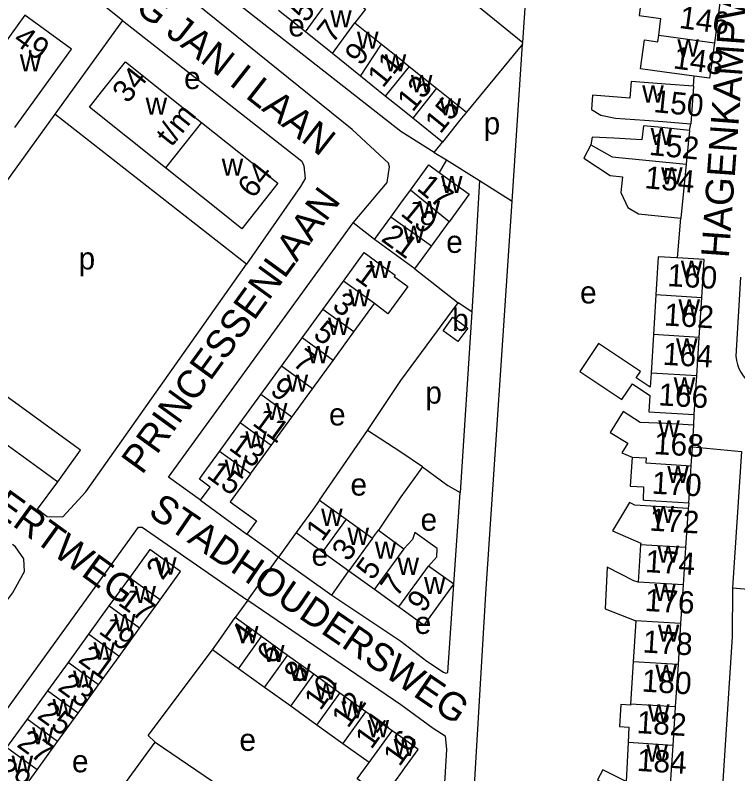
# Model space of a CAD drawing. Extents: x 159700 to 161346, y 381730 to 382922.
# Drawn here: x 160430.8 to 160560.5, y 382445.9 to 382582.1 of the extents above; entities that cross this region are included whole.
import ezdxf

# ---------------------------------------------------------------- set-up
doc = ezdxf.new("R2010")
doc.units = 0
for name, color, linetype in [('BLT_Basislijn', 7, 'Continuous'), ('BLT_Bebouwing', 7, 'Continuous'), ('BLT_Centroide', 7, 'Continuous'), ('BLT_Huisnummer', 7, 'Continuous'), ('BLT_Huisnummer_ tussenligend', 7, 'Continuous'), ('BLT_Huisnummer_reeks', 7, 'Continuous'), ('BLT_Onderverdeling_panden', 7, 'Continuous'), ('BLT_Straatnaam', 7, 'Continuous'), ('BLT_Vlakafsluiter', 7, 'Continuous')]:
    doc.layers.add(name, color=color, linetype=linetype)

msp = doc.modelspace()

# ---------------------------------------------------------------- linework, layer by layer
at = {"layer": 'BLT_Basislijn'}
for p, q in [((160521.9, 382577.2), (160522.55, 382587.01)), ((160450.08, 382581.13), (160437.89, 382564.3)), ((160521.88, 382576.89), (160511.79, 382564.68)), ((160521.88, 382576.89), (160521.9, 382577.2)), ((160552.56, 382569.33), (160552.67, 382571.16)), ((160472.29, 382537.4), (160437.89, 382564.3)), ((160551.83, 382561.41), (160552.04, 382562.6)), ((160506.02, 382557.47), (160507.48, 382559.32)), ((160506.02, 382557.47), (160508.2, 382556.11)), ((160508.2, 382556.11), (160506.92, 382553.88)), ((160508.2, 382556.11), (160514.16, 382552.39)), ((160514.16, 382552.39), (160519.99, 382548.74)), ((160495.27, 382541.84), (160491.46, 382544.8)), ((160549.67, 382538.56), (160550.27, 382545.68)), ((160502.54, 382536.57), (160510.32, 382530.44)), ((160560.96, 382535.06), (160560.13, 382520.87)), ((160512.73, 382528.86), (160510.32, 382530.44)), ((160512.73, 382528.86), (160510.64, 382496.44)), ((160552.6, 382508.49), (160552.67, 382510.41)), ((160485.43, 382495.06), (160494.02, 382507.56)), ((160552.35, 382504.63), (160561.18, 382503.79)), ((160561.18, 382503.79), (160559.55, 382479.31)), ((160464.08, 382495.04), (160458.31, 382499.17)), ((160434.82, 382493.43), (160438.44, 382498.36)), ((160509.52, 382479.96), (160510.64, 382496.44)), ((160551.7, 382494.52), (160551.58, 382493.56)), ((160477.01, 382485.58), (160472.36, 382488.95)), ((160481.23, 382489.22), (160478.07, 382484.82)), ((160477.01, 382485.58), (160478.07, 382484.82)), ((160478.07, 382484.82), (160487.6, 382477.99)), ((160487.6, 382477.99), (160490.7, 382482.38)), ((160559.55, 382479.31), (160564.17, 382478.9)), ((160472.54, 382477.1), (160470.28, 382473.97)), ((160455.93, 382451.62), (160486.17, 382431.07))]:
    msp.add_line(p, q, dxfattribs=at)
for points in [[(160482.89, 382608.65), (160500, 382594.99), (160521.9, 382577.2)], [(160491.46, 382544.8), (160497.56, 382552.05), (160497.99, 382554.89), (160497.77, 382555.53), (160491.25, 382561.57), (160440.32, 382602.72)], [(160450.08, 382581.13), (160435.03, 382593.18), (160433.21, 382592.93), (160424.89, 382581.85), (160387.63, 382530.18), (160388, 382528.33), (160391.85, 382526)], [(160506.02, 382557.47), (160500, 382561.24), (160466, 382587.92)], [(160450.08, 382581.13), (160482.23, 382555.86), (160482.6, 382555.07), (160482.81, 382552.8), (160482.02, 382551.33), (160472.29, 382537.4)], [(160519.99, 382548.74), (160521.88, 382576.89)], [(160437.89, 382564.3), (160411.53, 382527.84), (160403.97, 382516.97)], [(160514.16, 382552.39), (160512.98, 382532.81), (160512.73, 382528.86)], [(160512.9, 382437.77), (160515.27, 382478.21), (160519.99, 382548.74)], [(160458.31, 382499.17), (160491.46, 382544.8)], [(160434.82, 382493.43), (160436.55, 382492.11), (160439.35, 382492.08), (160443.49, 382496.52), (160472.29, 382537.4)], [(160494.02, 382507.56), (160500, 382516.52), (160510.32, 382530.44)], [(160560.13, 382520.87), (160560.24, 382520.12), (160560.44, 382519.39), (160560.71, 382518.68), (160561.05, 382518.01), (160561.46, 382517.37), (160561.94, 382516.78), (160562.47, 382516.25), (160563.06, 382515.77), (160563.7, 382515.36), (160564.38, 382515.02), (160565.08, 382514.76), (160565.82, 382514.56), (160566.57, 382514.45), (160567.08, 382514.42)], [(160503.93, 382501.04), (160500, 382503.69), (160494.02, 382507.56)], [(160503.93, 382501.04), (160500, 382495.65), (160495.98, 382489.64)], [(160503.93, 382501.04), (160508.47, 382497.7), (160510.64, 382496.44)], [(160430.4, 382416.72), (160418.93, 382425.29), (160413.76, 382429.1), (160410.56, 382431.49), (160411.73, 382433.33), (160452.93, 382490.2), (160453.57, 382490.2), (160472.31, 382477.25), (160472.54, 382477.1)], [(160423.27, 382469.03), (160430.29, 382478.37), (160432.44, 382482.25), (160432.32, 382484.51), (160430.82, 382486.67), (160430.3, 382487.08)], [(160487.6, 382477.99), (160500, 382469.72), (160504.66, 382466.15), (160507.69, 382464.21), (160508.1, 382464.02), (160508.46, 382464.1), (160509.52, 382479.96)], [(160559.55, 382479.31), (160559.48, 382470.53), (160555.29, 382405.8)], [(160472.54, 382477.1), (160500, 382458.38), (160505.82, 382454.14), (160507.95, 382452.76), (160508.2, 382450.32), (160507.17, 382433.33), (160506.17, 382416.78)], [(160455.93, 382451.62), (160454.67, 382452.8), (160466.18, 382468.17)], [(160432.72, 382419.8), (160442.6, 382433.33), (160455.93, 382451.62)]]:
    msp.add_lwpolyline(points, dxfattribs=at)
at = {"layer": 'BLT_Bebouwing'}
for p, q in [((160482.88, 382579.09), (160478.08, 382582.95)), ((160546.3, 382578.52), (160546.71, 382581.52)), ((160491.77, 382580.72), (160496.56, 382576.87)), ((160487.72, 382575.2), (160482.88, 382579.09)), ((160492.75, 382571.16), (160487.72, 382575.2)), ((160501.51, 382572.9), (160506.42, 382568.97)), ((160497.2, 382567.58), (160492.75, 382571.16)), ((160552.56, 382569.33), (160552.04, 382562.6)), ((160506.42, 382568.97), (160511.79, 382564.68)), ((160507.48, 382559.32), (160502.15, 382563.6)), ((160551.83, 382561.41), (160551.23, 382555.34)), ((160505.5, 382540.63), (160508.71, 382545.03)), ((160502.54, 382536.57), (160505.5, 382540.63)), ((160486.01, 382529.28), (160489.72, 382534.37)), ((160545.79, 382531.88), (160545.36, 382524.76)), ((160553.57, 382524.26), (160554.03, 382531.39)), ((160491.57, 382525.23), (160495.27, 382530.32)), ((160482.3, 382524.18), (160486.01, 382529.28)), ((160487.86, 382520.14), (160491.57, 382525.23)), ((160545.36, 382524.76), (160544.94, 382517.83)), ((160478.59, 382519.09), (160482.3, 382524.18)), ((160553.12, 382517.34), (160553.57, 382524.26)), ((160474.88, 382513.99), (160478.59, 382519.09)), ((160484.15, 382515.04), (160487.86, 382520.14)), ((160413.84, 382516.2), (160436.18, 382500)), ((160552.67, 382510.41), (160553.12, 382517.34)), ((160480.44, 382509.95), (160484.15, 382515.04)), ((160471.17, 382508.9), (160474.88, 382513.99)), ((160476.73, 382504.85), (160480.44, 382509.95)), ((160467.46, 382503.8), (160471.17, 382508.9)), ((160552.35, 382504.63), (160552.6, 382508.49)), ((160473.2, 382500), (160476.73, 382504.85)), ((160552.13, 382501.24), (160552.35, 382504.63)), ((160464.69, 382500), (160467.46, 382503.8)), ((160541.51, 382502.75), (160541.19, 382497.58)), ((160551.7, 382494.52), (160552.13, 382501.24)), ((160436.18, 382500), (160438.44, 382498.36)), ((160438.44, 382498.36), (160439.64, 382500)), ((160473.02, 382499.76), (160473.2, 382500)), ((160464.08, 382495.04), (160472.36, 382488.95)), ((160485.43, 382495.06), (160490.17, 382491.65)), ((160543.79, 382495.01), (160543.54, 382495.03)), ((160551.7, 382494.52), (160543.79, 382495.01)), ((160551.58, 382493.56), (160551.13, 382486.56)), ((160490.17, 382491.65), (160494.92, 382488.24)), ((160481.23, 382489.22), (160485.96, 382485.8)), ((160494.92, 382488.24), (160495.98, 382489.64)), ((160495.98, 382489.64), (160500.57, 382486.34)), ((160543.05, 382487.06), (160542.62, 382480.36)), ((160551.13, 382486.56), (160550.69, 382479.85)), ((160485.96, 382485.8), (160490.7, 382482.38)), ((160490.7, 382482.38), (160495.29, 382479.06)), ((160509.52, 382479.96), (160504.96, 382483.19)), ((160451.3, 382481.14), (160447.62, 382476.06)), ((160550.69, 382479.85), (160550.24, 382472.9)), ((160495.29, 382479.06), (160499.67, 382475.9)), ((160453.12, 382472.08), (160456.8, 382477.16)), ((160447.62, 382476.06), (160443.94, 382470.98)), ((160475.01, 382470.56), (160470.28, 382473.97)), ((160542.18, 382473.4), (160541.73, 382466.05)), ((160550.24, 382472.9), (160549.77, 382465.55)), ((160449.44, 382467), (160453.12, 382472.08)), ((160443.94, 382470.98), (160440.27, 382465.9)), ((160479.69, 382467.18), (160475.01, 382470.56)), ((160470.87, 382464.8), (160466.18, 382468.17)), ((160484.38, 382463.81), (160479.69, 382467.18)), ((160440.27, 382465.9), (160436.59, 382460.82)), ((160445.76, 382461.92), (160449.44, 382467)), ((160541.73, 382466.05), (160541.25, 382458.45)), ((160475.56, 382461.43), (160470.87, 382464.8)), ((160549.77, 382465.55), (160549.27, 382457.95)), ((160489.06, 382460.43), (160484.38, 382463.81)), ((160442.09, 382456.84), (160445.76, 382461.92)), ((160436.59, 382460.82), (160432.91, 382455.74)), ((160480.24, 382458.06), (160475.56, 382461.43)), ((160493.75, 382457.06), (160489.06, 382460.43)), ((160484.93, 382454.69), (160480.24, 382458.06)), ((160549.27, 382457.95), (160548.83, 382451.03)), ((160438.41, 382451.76), (160442.09, 382456.84)), ((160498.44, 382453.68), (160493.75, 382457.06)), ((160432.91, 382455.74), (160429.23, 382450.66)), ((160489.62, 382451.32), (160484.93, 382454.69)), ((160434.73, 382446.68), (160438.41, 382451.76)), ((160494.32, 382447.95), (160489.62, 382451.32)), ((160540.79, 382451.53), (160540.45, 382444.54)), ((160548.83, 382451.03), (160548.37, 382444.04)), ((160431.05, 382441.6), (160434.73, 382446.68))]:
    msp.add_line(p, q, dxfattribs=at)
for points in [[(160544.03, 382592.06), (160542.8, 382582.06), (160546.71, 382581.52)], [(160486.92, 382584.62), (160488.8, 382586.98), (160493.69, 382583.14), (160491.77, 382580.72)], [(160553.63, 382585.21), (160557.34, 382584.7), (160556.29, 382577.15)], [(160430.72, 382561.95), (160440.9, 382575.98), (160432.49, 382582.07), (160422.32, 382568.04)], [(160552.67, 382571.16), (160550.46, 382571.46), (160547.36, 382571.89), (160543.06, 382572.48), (160543.77, 382577.65)], [(160543.77, 382577.65), (160546.14, 382577.33), (160546.3, 382578.52)], [(160496.56, 382576.87), (160500, 382574.11), (160501.51, 382572.9)], [(160556.29, 382577.15), (160555.42, 382570.78), (160552.67, 382571.16)], [(160457.78, 382554.69), (160444.11, 382565.6), (160446.3, 382568.35), (160450.61, 382573.72), (160464.26, 382562.82)], [(160552.56, 382569.33), (160547.58, 382569.72), (160541.33, 382570.21), (160541.09, 382567.2)], [(160502.15, 382563.6), (160500, 382565.33), (160497.2, 382567.58)], [(160541.09, 382567.2), (160534.42, 382567.72), (160534.23, 382565.18), (160535.94, 382564.17), (160538.54, 382563.61), (160543.73, 382563.25), (160547.06, 382562.99), (160552.04, 382562.6)], [(160511.79, 382564.68), (160510.61, 382563.22), (160507.48, 382559.32)], [(160464.26, 382562.82), (160477.92, 382551.92), (160471.46, 382543.77), (160467.46, 382546.96), (160457.78, 382554.69)], [(160551.83, 382561.41), (160546.85, 382561.91), (160543.55, 382562.23), (160543.3, 382559.73), (160538.26, 382560), (160534.37, 382560.2), (160534.13, 382558.83)], [(160534.13, 382558.83), (160532.86, 382556.42), (160537.6, 382553.3), (160539.81, 382553.09), (160539.53, 382550.28), (160540.74, 382547.57), (160542.7, 382546.42), (160550.27, 382545.68)], [(160501.72, 382550.71), (160505.04, 382555.26), (160506.92, 382553.88)], [(160551.23, 382555.34), (160550.27, 382545.68)], [(160506.92, 382553.88), (160509.07, 382552.31), (160512.29, 382549.95), (160508.71, 382545.03)], [(160498.19, 382545.85), (160500, 382548.34), (160501.72, 382550.71)], [(160495.27, 382541.84), (160498.19, 382545.85)], [(160502.54, 382536.57), (160495.27, 382541.84)], [(160489.72, 382534.37), (160493.46, 382539.51), (160497.47, 382536.53), (160498.98, 382535.41), (160498.8, 382535.17), (160501.25, 382533.39), (160497.7, 382528.51), (160495.27, 382530.32)], [(160549.67, 382538.56), (160549.57, 382538.56), (160546.2, 382538.72), (160545.79, 382531.88)], [(160554.03, 382531.39), (160554.48, 382538.27), (160549.67, 382538.56)], [(160544.94, 382517.83), (160544.79, 382515.31), (160542.28, 382516.98), (160543.06, 382518.15), (160535.49, 382523.19), (160532.14, 382518.15), (160539.71, 382513.12), (160541.57, 382515.9), (160544.7, 382513.82), (160544.52, 382510.9), (160552.67, 382510.41)], [(160439.64, 382500), (160442.54, 382504), (160417.93, 382521.84), (160413.84, 382516.2)], [(160552.6, 382508.49), (160547.61, 382508.79), (160542.98, 382508.97), (160539.9, 382510.94), (160537.58, 382507.18), (160540.73, 382505.29), (160539.68, 382503.54), (160541.51, 382502.75)], [(160464.08, 382495.04), (160465.81, 382497.41), (160463.85, 382498.84), (160464.69, 382500)], [(160473.02, 382499.76), (160472.26, 382498.71), (160469.39, 382494.76), (160474.09, 382491.33), (160472.36, 382488.95)], [(160541.19, 382497.58), (160543.59, 382497.43), (160543.54, 382495.03)], [(160485.43, 382495.06), (160484.15, 382493.28), (160481.23, 382489.22)], [(160551.58, 382493.56), (160542.01, 382494.15), (160541.03, 382494.66), (160537.98, 382489.54), (160543.07, 382487.31), (160543.05, 382487.06)], [(160504.96, 382483.19), (160506.45, 382484.89), (160506.55, 382486.35), (160502.51, 382489.24), (160502.08, 382488.01), (160500.57, 382486.34)], [(160456.8, 382477.16), (160460.47, 382482.23), (160454.98, 382486.21), (160451.3, 382481.14)], [(160542.62, 382480.36), (160541.86, 382480.55), (160537.06, 382483.04), (160536.66, 382475.53), (160542.18, 382473.4)], [(160499.67, 382475.9), (160500, 382475.66), (160504.2, 382472.62), (160507.12, 382476.68), (160509.52, 382479.96)], [(160466.18, 382468.17), (160467.39, 382469.89), (160470.28, 382473.97)], [(160541.25, 382458.45), (160541.24, 382458.25), (160539.51, 382458.36), (160539.26, 382454.43), (160540.96, 382454.33), (160540.79, 382451.53)], [(160500.73, 382446.99), (160503.11, 382450.32), (160500, 382452.55), (160498.44, 382453.68)], [(160496.92, 382441.69), (160492.15, 382445.02), (160494.32, 382447.95)], [(160496.92, 382441.69), (160500, 382445.97), (160500.73, 382446.99)], [(160540.45, 382444.54), (160536.25, 382446.67), (160535.32, 382444.84), (160536.05, 382444.46), (160534.32, 382441.05), (160540.06, 382438.14), (160540.03, 382437.64), (160547.92, 382437.12)]]:
    msp.add_lwpolyline(points, dxfattribs=at)
msp.add_lwpolyline([(160507.59, 382525.44), (160509.34, 382527.87), (160512.02, 382525.94), (160510.27, 382523.51)], close=True, dxfattribs=at)
at = {"layer": 'BLT_Onderverdeling_panden'}
for p, q in [((160482.88, 382579.09), (160486.92, 382584.62)), ((160487.72, 382575.2), (160491.77, 382580.72)), ((160546.3, 382578.52), (160556.29, 382577.15)), ((160492.75, 382571.16), (160496.56, 382576.87)), ((160501.51, 382572.9), (160497.2, 382567.58)), ((160506.42, 382568.97), (160502.15, 382563.6)), ((160464.26, 382562.82), (160457.78, 382554.69)), ((160508.71, 382545.03), (160501.72, 382550.71)), ((160505.5, 382540.63), (160498.19, 382545.85)), ((160495.27, 382530.32), (160489.72, 382534.37)), ((160554.03, 382531.39), (160545.79, 382531.88)), ((160491.57, 382525.23), (160486.01, 382529.28)), ((160553.57, 382524.26), (160545.36, 382524.76)), ((160487.86, 382520.14), (160482.3, 382524.18)), ((160484.15, 382515.04), (160478.59, 382519.09)), ((160553.12, 382517.34), (160544.94, 382517.83)), ((160480.44, 382509.95), (160474.88, 382513.99)), ((160476.73, 382504.85), (160471.17, 382508.9)), ((160473.02, 382499.76), (160467.46, 382503.8)), ((160490.17, 382491.65), (160485.96, 382485.8)), ((160494.92, 382488.24), (160490.7, 382482.38)), ((160500.57, 382486.34), (160495.29, 382479.06)), ((160551.13, 382486.56), (160543.05, 382487.06)), ((160499.67, 382475.9), (160504.96, 382483.19)), ((160456.8, 382477.16), (160451.3, 382481.14)), ((160550.69, 382479.85), (160542.62, 382480.36)), ((160453.12, 382472.08), (160447.62, 382476.06)), ((160550.24, 382472.9), (160542.18, 382473.4)), ((160449.44, 382467), (160443.94, 382470.98)), ((160470.87, 382464.8), (160475.01, 382470.56)), ((160475.56, 382461.43), (160479.69, 382467.18)), ((160445.76, 382461.92), (160440.27, 382465.9)), ((160549.77, 382465.55), (160541.73, 382466.05)), ((160480.24, 382458.06), (160484.38, 382463.81)), ((160442.09, 382456.84), (160436.59, 382460.82)), ((160484.93, 382454.69), (160489.06, 382460.43)), ((160549.27, 382457.95), (160541.25, 382458.45)), ((160489.62, 382451.32), (160493.75, 382457.06)), ((160438.41, 382451.76), (160432.91, 382455.74)), ((160494.32, 382447.95), (160498.44, 382453.68)), ((160548.83, 382451.03), (160540.79, 382451.53)), ((160434.73, 382446.68), (160429.23, 382450.66))]:
    msp.add_line(p, q, dxfattribs=at)
for points in [[(160534.13, 382558.83), (160537.93, 382556.65), (160551.23, 382555.34)], [(160541.51, 382502.75), (160544.04, 382502.62), (160543.96, 382501.72), (160552.13, 382501.24)]]:
    msp.add_lwpolyline(points, dxfattribs=at)
at = {"layer": 'BLT_Vlakafsluiter'}
msp.add_line((160472.54, 382477.1), (160478.07, 382484.82), dxfattribs=at)

# ---------------------------------------------------------------- texts
at = {"layer": 'BLT_Centroide'}
for s, p in [('w', (160487.33, 382579.91)), ('e', (160479.81, 382578.28)), ('w', (160492.14, 382576.05)), ('w', (160549.66, 382574.66)), ('w', (160431.61, 382572)), ('w', (160497.12, 382572.02)), ('e', (160461.11, 382568.83)), ('w', (160501.81, 382568.27)), ('w', (160543.34, 382566.41)), ('w', (160454.2, 382564.22)), ('w', (160506.97, 382564.12)), ('p', (160514.88, 382560.7)), ('w', (160544.85, 382558.78)), ('w', (160467.86, 382553.28)), ('w', (160546.73, 382551.72)), ('w', (160507.22, 382550.16)), ('w', (160503.18, 382545.66)), ('w', (160500.41, 382541.22)), ('e', (160508.16, 382539.43)), ('p', (160442.17, 382536.45)), ('w', (160494.37, 382534.91)), ('w', (160550.27, 382534.97)), ('w', (160490.64, 382529.81)), ('e', (160532.18, 382530.35)), ('w', (160549.85, 382528)), ('b', (160509.23, 382525.42)), ('w', (160486.93, 382524.72)), ('w', (160549.42, 382521)), ('w', (160483.23, 382519.62)), ('w', (160479.52, 382514.53)), ('w', (160549, 382514)), ('p', (160504.41, 382512.37)), ('w', (160475.8, 382509.44)), ('e', (160487.12, 382508.46)), ('w', (160546.22, 382506.31)), ('w', (160472.1, 382504.34)), ('w', (160468.39, 382499.25)), ('w', (160547.83, 382498.12)), ('e', (160490.97, 382495.87)), ('w', (160485.7, 382490.44)), ('w', (160545.19, 382490.94)), ('e', (160503.55, 382489.57)), ('w', (160490.44, 382487.02)), ('w', (160495.34, 382484.55)), ('e', (160483.98, 382483.28)), ('w', (160546.08, 382483.81)), ('w', (160455.89, 382481.69)), ('w', (160499.41, 382481.64)), ('w', (160504.17, 382478.2)), ('w', (160452.2, 382476.59)), ('w', (160545.5, 382476.94)), ('w', (160448.53, 382471.53)), ('e', (160502.5, 382471.04)), ('w', (160546.16, 382469.66)), ('w', (160470.59, 382469.38)), ('w', (160444.85, 382466.44)), ('w', (160475.28, 382466)), ('w', (160441.17, 382461.38)), ('w', (160479.97, 382462.62)), ('w', (160545.7, 382462.47)), ('w', (160484.66, 382459.25)), ('w', (160437.5, 382456.28)), ('w', (160489.34, 382455.88)), ('w', (160544.38, 382455.31)), ('w', (160494.03, 382452.5)), ('w', (160433.82, 382451.22)), ('e', (160471.04, 382450.05)), ('w', (160498.72, 382449.12)), ('w', (160544.08, 382448.12)), ('w', (160430.14, 382446.12)), ('e', (160440.98, 382446.21))]:
    msp.add_text(s, height=4, dxfattribs=at).set_placement(p)
at = {"layer": 'BLT_Huisnummer'}
for s, rotation, p in [('5', 51.2106, (160482.99, 382580.59)), ('146', 352.1599, (160549.84, 382579.81)), ('9', 51.2079, (160492.74, 382572.83)), ('148', 352.1542, (160548.77, 382572.57)), ('150', 354.3635, (160545.26, 382564.71)), ('15', 51.1935, (160507.11, 382560.64)), ('154', 354.375, (160543.67, 382551.06)), ('17', 320.8879, (160502.7, 382550.82)), ('21', 324.0375, (160496.29, 382541.7)), ('1', 323.9396, (160491.56, 382534.82)), ('160', 356.5519, (160547.77, 382533.48)), ('5', 323.9463, (160484.08, 382524.39)), ('9', 323.9481, (160476.34, 382514.3)), ('166', 356.5528, (160546.16, 382512.08)), ('168', 356.6012, (160545.36, 382503.32)), ('15', 323.8483, (160464.98, 382499.23)), ('172', 356.4367, (160544.55, 382489.6)), ('1', 54.2887, (160485.89, 382487.43)), ('5', 54.2888, (160494.93, 382480.5)), ('2', 54.0931, (160457.23, 382480.51)), ('9', 54.3424, (160504.08, 382474.66)), ('176', 356.438, (160543.71, 382475.18)), ('19', 324.0905, (160445.59, 382471.27)), ('4', 54.2886, (160472.41, 382468.83)), ('8', 54.2892, (160481.94, 382461.97)), ('180', 356.438, (160543.17, 382460.71)), ('23', 324.0905, (160438.22, 382461.1)), ('12', 54.2898, (160490.52, 382453.97)), ('27', 324.0924, (160430.9, 382450.94)), ('16', 54.4399, (160499.77, 382447.09)), ('184', 356.4375, (160542.31, 382446.47))]:
    msp.add_text(s, height=4, rotation=rotation, dxfattribs=at).set_placement(p)
at = {"layer": 'BLT_Huisnummer_ tussenligend'}
for s, rotation, p in [('7', 51.2106, (160487.76, 382576.86)), ('11', 51.2079, (160496.79, 382568.88)), ('13', 51.2106, (160502.13, 382564.55)), ('152', 354.3635, (160544.46, 382557.03)), ('19', 320.8879, (160499.79, 382546.3)), ('3', 323.9396, (160487.49, 382529.51)), ('162', 356.5519, (160547.18, 382526.41)), ('164', 356.5528, (160546.97, 382519.36)), ('7', 323.9463, (160480.36, 382519.36)), ('11', 323.9481, (160473.18, 382508.64)), ('13', 323.95, (160468.94, 382504.24)), ('170', 356.6012, (160544.98, 382496.23)), ('3', 54.2881, (160490.57, 382483.87)), ('174', 356.4367, (160543.81, 382482.15)), ('7', 54.2888, (160499.29, 382477.47)), ('17', 324.0905, (160449.06, 382476.4)), ('178', 356.438, (160543.35, 382467.73)), ('21', 324.0905, (160441.9, 382466.12)), ('6', 54.2886, (160477.08, 382465.36)), ('10', 54.2892, (160485.57, 382457.13)), ('25', 324.0924, (160434.53, 382456.06)), ('14', 54.2898, (160494.73, 382450.18)), ('182', 356.438, (160542.27, 382453.26)), ('29', 324.0924, (160426.95, 382445.94))]:
    msp.add_text(s, height=4, rotation=rotation, dxfattribs=at).set_placement(p)
at = {"layer": 'BLT_Huisnummer_reeks'}
for s, rotation, p in [('49', 324.0721, (160430.21, 382577.23)), ('34', 51.257, (160450.99, 382566.09)), ('t/m', 51.4073, (160458.84, 382558.31)), ('64', 51.5717, (160473.5, 382549.02))]:
    msp.add_text(s, height=4, rotation=rotation, dxfattribs=at).set_placement(p)
at = {"layer": 'BLT_Straatnaam'}
for s, height, rotation, p in [('HAGENKAMPWEG ZUID', 4.9999, 85.8442, (160558.88, 382538.42)), ('HERTOG JAN I LAAN', 5, 321.834, (160433.68, 382597.47)), ('PRINCESSENLAAN', 5, 54.0111, (160453.57, 382499.46)), ('AARTSHERTOG ALBERTWEG', 5, 324.0579, (160373.56, 382531.56)), ('STADHOUDERSWEG', 5, 325.7305, (160454.44, 382492.45))]:
    msp.add_text(s, height=height, rotation=rotation, dxfattribs=at).set_placement(p)

doc.saveas('drawing.dxf')
